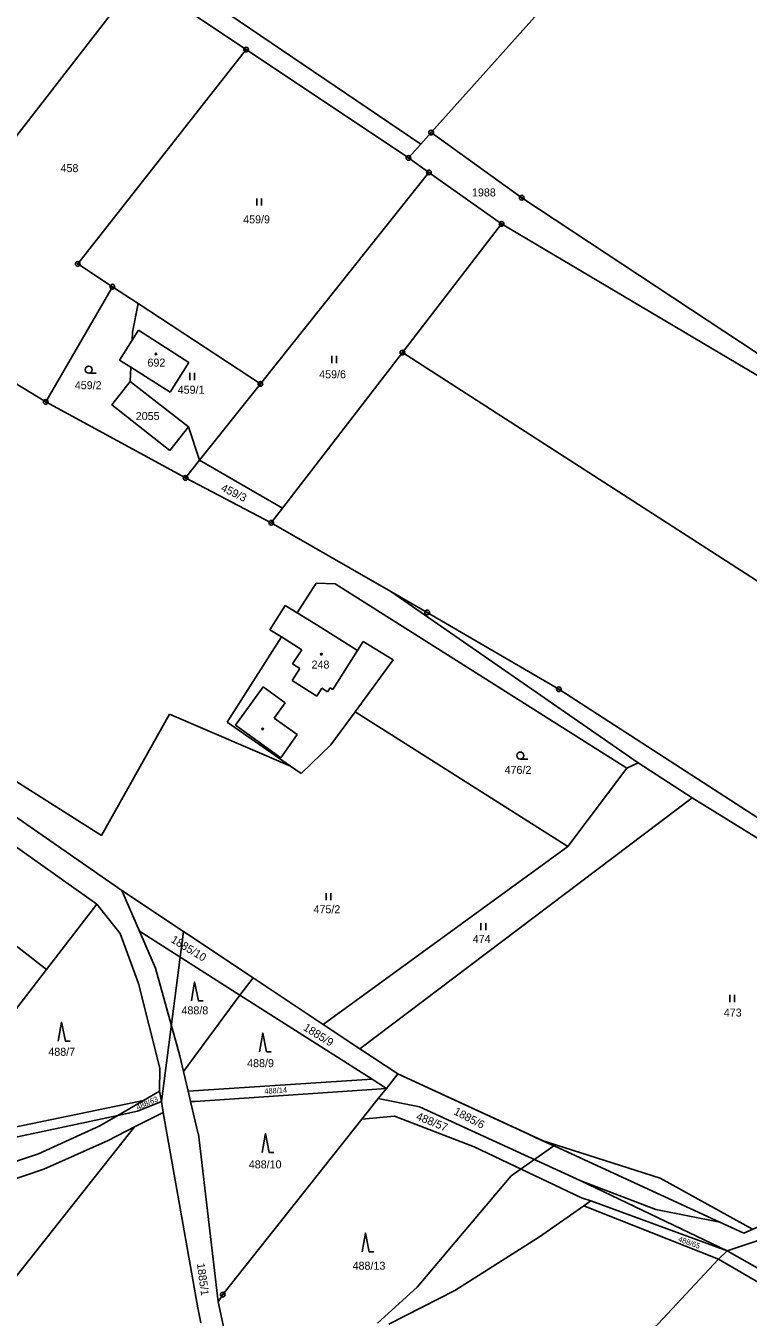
# Model space of a CAD drawing. Extents: x -445050 to -440454, y -1134563 to -1129741.
# Drawn here: x -442735.6 to -442582.2, y -1131669.9 to -1131395.6 of the extents above; entities that cross this region are included whole.
import ezdxf

# ---------------------------------------------------------------- set-up
doc = ezdxf.new("R2010")
doc.units = 0
for name, color, linetype in [('Vrstva 1', 7, 'Continuous'), ('Vrstva 16', 7, 'Continuous'), ('Vrstva 18', 7, 'Continuous'), ('Vrstva 19', 7, 'Continuous'), ('Vrstva 24', 7, 'Continuous'), ('Vrstva 25', 7, 'Continuous'), ('Vrstva 3', 7, 'Continuous'), ('Vrstva 37', 7, 'Continuous'), ('Vrstva 4', 7, 'Continuous'), ('Vrstva 52', 7, 'Continuous')]:
    doc.layers.add(name, color=color, linetype=linetype)

msp = doc.modelspace()

# ---------------------------------------------------------------- linework, layer by layer
at = {"layer": 'Vrstva 1'}
for p, q in [((-442713.03, -1131462.31), (-442712.95, -1131460.66)), ((-442711.72, -1131460.25), (-442700.99, -1131467.07)), ((-442713.31, -1131468.11), (-442713.45, -1131471.14)), ((-442700.99, -1131467.07), (-442705.01, -1131473.39))]:
    msp.add_line(p, q, dxfattribs=at)
for points in [[(-442651.76, -1131420.72), (-442778.95, -1131334.51)], [(-442605.47, -1131368.99), (-442649.54, -1131418.23)], [(-442765.47, -1131454.74), (-442711.64, -1131385.39)], [(-442711.64, -1131385.39), (-442688.85, -1131400.6)], [(-442688.85, -1131400.6), (-442724.6, -1131446.15)], [(-442688.85, -1131400.6), (-442654.36, -1131423.62)], [(-442649.54, -1131418.23), (-442651.76, -1131420.72)], [(-442630.31, -1131432.09), (-442649.54, -1131418.23)], [(-442651.76, -1131420.72), (-442654.36, -1131423.62)], [(-442654.36, -1131423.62), (-442650.02, -1131426.7)], [(-442685.81, -1131471.64), (-442650.02, -1131426.7)], [(-442650.02, -1131426.7), (-442634.59, -1131437.65)], [(-442562.37, -1131476.91), (-442630.31, -1131432.09)], [(-442634.59, -1131437.65), (-442655.64, -1131464.97)], [(-442564.05, -1131479.38), (-442634.59, -1131437.65)], [(-442724.6, -1131446.15), (-442717.25, -1131450.98)], [(-442717.25, -1131450.98), (-442731.4, -1131475.46)], [(-442717.25, -1131450.98), (-442711.81, -1131454.56)], [(-442711.81, -1131454.56), (-442712.95, -1131460.66)], [(-442711.81, -1131454.56), (-442685.81, -1131471.64)], [(-442765.47, -1131454.74), (-442731.4, -1131475.46)], [(-442715.73, -1131466.57), (-442713.03, -1131462.31)], [(-442713.03, -1131462.31), (-442711.72, -1131460.25)], [(-442655.64, -1131464.97), (-442681.13, -1131498.05)], [(-442505.47, -1131561.71), (-442655.64, -1131464.97)], [(-442715.73, -1131466.57), (-442713.31, -1131468.11)], [(-442713.31, -1131468.11), (-442705.01, -1131473.39)], [(-442717.35, -1131476.11), (-442713.45, -1131471.14)], [(-442713.45, -1131471.14), (-442701.08, -1131480.76)], [(-442698.74, -1131487.87), (-442685.81, -1131471.64)], [(-442731.4, -1131475.46), (-442701.71, -1131491.6)], [(-442717.35, -1131476.11), (-442705.03, -1131485.78)], [(-442705.03, -1131485.78), (-442701.08, -1131480.76)], [(-442701.08, -1131480.76), (-442698.74, -1131487.87)], [(-442701.71, -1131491.6), (-442698.74, -1131487.87)], [(-442698.74, -1131487.87), (-442681.13, -1131498.05)], [(-442701.71, -1131491.6), (-442683.5, -1131501.12)], [(-442681.13, -1131498.05), (-442683.5, -1131501.12)], [(-442683.5, -1131501.12), (-442658.12, -1131515.73)], [(-442674, -1131513.97), (-442678.01, -1131520.24)], [(-442669.93, -1131514.08), (-442674, -1131513.97)], [(-442607.99, -1131553.24), (-442669.93, -1131514.08)], [(-442650.39, -1131520.18), (-442658.12, -1131515.73)], [(-442605.54, -1131552.11), (-442658.12, -1131515.73)], [(-442680.56, -1131518.68), (-442683.79, -1131523.85)], [(-442678.01, -1131520.24), (-442680.56, -1131518.68)], [(-442673.59, -1131522.94), (-442678.01, -1131520.24)], [(-442650.39, -1131520.18), (-442622.41, -1131536.5)], [(-442673.59, -1131522.94), (-442665.19, -1131528.29)], [(-442681.32, -1131525.4), (-442692.9, -1131543.48)], [(-442683.79, -1131523.85), (-442681.32, -1131525.4)], [(-442665.19, -1131528.29), (-442663.95, -1131526.35)], [(-442663.95, -1131526.35), (-442657.58, -1131530.23)], [(-442657.58, -1131530.23), (-442665.71, -1131541.3)], [(-442556.5, -1131579.12), (-442622.41, -1131536.5)], [(-442769.33, -1131541.71), (-442715.22, -1131579.29)], [(-442762.98, -1131540.07), (-442719.6, -1131567.6)], [(-442719.6, -1131567.6), (-442705.11, -1131541.83)], [(-442705.11, -1131541.83), (-442679.44, -1131552.84)], [(-442665.71, -1131541.3), (-442670.87, -1131548.32)], [(-442665.71, -1131541.3), (-442620.52, -1131569.9)], [(-442692.9, -1131543.48), (-442679.44, -1131552.84)], [(-442670.87, -1131548.32), (-442677.19, -1131554.4)], [(-442679.44, -1131552.84), (-442677.19, -1131554.4)], [(-442620.52, -1131569.9), (-442607.99, -1131553.24)], [(-442607.99, -1131553.24), (-442605.54, -1131552.11)], [(-442594.09, -1131559.59), (-442605.54, -1131552.11)], [(-442758.42, -1131555.33), (-442720.56, -1131582.16)], [(-442594.09, -1131559.59), (-442664.68, -1131612.89)], [(-442594.09, -1131559.59), (-442506.26, -1131613.79)], [(-442672.47, -1131607.71), (-442620.52, -1131569.9)], [(-442715.22, -1131579.29), (-442687.37, -1131597.8)], [(-442711.5, -1131587.93), (-442715.22, -1131579.29)], [(-442720.56, -1131582.16), (-442731.23, -1131596.02)], [(-442715.62, -1131588.42), (-442720.56, -1131582.16)], [(-442744.14, -1131586.06), (-442731.23, -1131596.02)], [(-442711.69, -1131598.98), (-442715.62, -1131588.42)], [(-442690.15, -1131601.52), (-442711.5, -1131587.93)], [(-442708.13, -1131595.77), (-442711.5, -1131587.93)], [(-442742.62, -1131610.8), (-442731.23, -1131596.02)], [(-442702.94, -1131614.39), (-442708.13, -1131595.77)], [(-442707.18, -1131616.97), (-442711.69, -1131598.98)], [(-442687.37, -1131597.8), (-442690.15, -1131601.52)], [(-442687.37, -1131597.8), (-442672.47, -1131607.71)], [(-442690.15, -1131601.52), (-442702.15, -1131617.73)], [(-442662.1, -1131619.36), (-442690.15, -1131601.52)], [(-442672.47, -1131607.71), (-442664.68, -1131612.89)], [(-442664.68, -1131612.89), (-442656.65, -1131618.23)], [(-442702.15, -1131617.73), (-442702.94, -1131614.39)], [(-442707.25, -1131621.9), (-442707.18, -1131616.97)], [(-442701.16, -1131621.91), (-442702.15, -1131617.73)], [(-442656.65, -1131618.23), (-442659.05, -1131621.3)], [(-442656.65, -1131618.23), (-442588.22, -1131649.72)], [(-442707.25, -1131621.9), (-442710.63, -1131623.87)], [(-442706.86, -1131624.1), (-442707.25, -1131621.9)], [(-442662.1, -1131619.36), (-442701.16, -1131621.91)], [(-442700.64, -1131624.1), (-442701.16, -1131621.91)], [(-442659.05, -1131621.3), (-442699.66, -1131624.1)], [(-442659.05, -1131621.3), (-442662.1, -1131619.36)], [(-442659.05, -1131621.3), (-442660.8, -1131623.46)], [(-442710.63, -1131623.87), (-442744.23, -1131630.81)], [(-442710.63, -1131623.87), (-442716.12, -1131627.06)], [(-442711.91, -1131626.17), (-442706.86, -1131624.1)], [(-442706.45, -1131626.39), (-442706.86, -1131624.1)], [(-442699.03, -1131630.93), (-442700.64, -1131624.1)], [(-442699.66, -1131624.1), (-442700.64, -1131624.1)], [(-442664.24, -1131627.84), (-442660.8, -1131623.46)], [(-442652.04, -1131625.21), (-442660.8, -1131623.46)], [(-442743.17, -1131632.81), (-442716.12, -1131627.06)], [(-442716.12, -1131627.06), (-442719.91, -1131629.27)], [(-442716.12, -1131627.06), (-442711.91, -1131626.17)], [(-442712.53, -1131629.48), (-442706.45, -1131626.39)], [(-442699.12, -1131667.9), (-442706.45, -1131626.39)], [(-442657.35, -1131627.22), (-442664.24, -1131627.84)], [(-442640.38, -1131633.71), (-442657.35, -1131627.22)], [(-442617.77, -1131640.95), (-442652.04, -1131625.21)], [(-442753.33, -1131680.95), (-442712.53, -1131629.48)], [(-442719.91, -1131629.27), (-442732.93, -1131635.18)], [(-442718.17, -1131632.34), (-442712.53, -1131629.48)], [(-442693.82, -1131665.09), (-442664.24, -1131627.84)], [(-442731.84, -1131638.47), (-442718.17, -1131632.34)], [(-442698.99, -1131631.05), (-442699.03, -1131630.93)], [(-442694.81, -1131666.64), (-442698.99, -1131631.05)], [(-442732.93, -1131635.18), (-442761.97, -1131644.83)], [(-442617.58, -1131644.58), (-442640.38, -1131633.71)], [(-442760.3, -1131648.07), (-442731.84, -1131638.47)], [(-442601.79, -1131647.01), (-442617.77, -1131640.95)], [(-442617.77, -1131640.95), (-442586.64, -1131655.78)], [(-442583.14, -1131652.06), (-442560.23, -1131641.95)], [(-442617.09, -1131646.24), (-442626.54, -1131652.86)], [(-442615.59, -1131645.21), (-442617.58, -1131644.58)], [(-442617.09, -1131646.24), (-442615.59, -1131645.21)], [(-442588.49, -1131657.59), (-442617.09, -1131646.24)], [(-442615.59, -1131645.21), (-442586.64, -1131655.78)], [(-442588.22, -1131649.72), (-442601.79, -1131647.01)], [(-442586.64, -1131655.78), (-442559.37, -1131646.74)], [(-442583.14, -1131652.06), (-442588.22, -1131649.72)], [(-442626.54, -1131652.86), (-442644.49, -1131664.21)], [(-442605.32, -1131675.53), (-442588.49, -1131657.59)], [(-442586.64, -1131655.78), (-442588.49, -1131657.59)], [(-442506.53, -1131705.31), (-442588.49, -1131657.59)], [(-442553.17, -1131674.75), (-442586.64, -1131655.78)], [(-442694.81, -1131666.64), (-442693.82, -1131665.09)], [(-442644.49, -1131664.21), (-442658.53, -1131671.42)], [(-442698.48, -1131671.11), (-442699.12, -1131667.9)], [(-442694.81, -1131666.64), (-442691.36, -1131682.4)]]:
    msp.add_lwpolyline(points, dxfattribs=at)
at = {"layer": 'Vrstva 24'}
for centre, radius in [((-442688.85, -1131400.6), 0.5), ((-442688.85, -1131400.6), 0.1), ((-442649.54, -1131418.23), 0.5), ((-442649.54, -1131418.23), 0.1), ((-442654.36, -1131423.62), 0.5), ((-442654.36, -1131423.62), 0.1), ((-442650.02, -1131426.7), 0.5), ((-442650.02, -1131426.7), 0.1), ((-442630.31, -1131432.09), 0.5), ((-442630.31, -1131432.09), 0.1), ((-442634.59, -1131437.65), 0.5), ((-442634.59, -1131437.65), 0.1), ((-442724.6, -1131446.15), 0.5), ((-442724.6, -1131446.15), 0.1), ((-442717.25, -1131450.98), 0.5), ((-442717.25, -1131450.98), 0.1), ((-442655.64, -1131464.97), 0.5), ((-442655.64, -1131464.97), 0.1), ((-442685.81, -1131471.64), 0.5), ((-442685.81, -1131471.64), 0.1), ((-442731.4, -1131475.46), 0.5), ((-442731.4, -1131475.46), 0.1), ((-442701.71, -1131491.6), 0.5), ((-442701.71, -1131491.6), 0.1), ((-442683.5, -1131501.12), 0.5), ((-442683.5, -1131501.12), 0.1), ((-442650.39, -1131520.18), 0.5), ((-442650.39, -1131520.18), 0.1), ((-442622.41, -1131536.5), 0.5), ((-442622.41, -1131536.5), 0.1), ((-442693.82, -1131665.09), 0.5), ((-442693.82, -1131665.09), 0.1)]:
    msp.add_circle(centre, radius, dxfattribs=at)
at = {"layer": 'Vrstva 25'}
for p, q in [((-442686.58, -1131433.71), (-442686.58, -1131432.21)), ((-442685.58, -1131433.71), (-442685.58, -1131432.21)), ((-442670.62, -1131467.2), (-442670.62, -1131465.7)), ((-442669.62, -1131467.2), (-442669.62, -1131465.7)), ((-442722.28, -1131469.35), (-442720.68, -1131469.35)), ((-442700.78, -1131470.81), (-442700.78, -1131469.31)), ((-442699.78, -1131470.81), (-442699.78, -1131469.31)), ((-442630.61, -1131551.34), (-442629.01, -1131551.34)), ((-442671.88, -1131581.33), (-442671.88, -1131579.83)), ((-442670.88, -1131581.33), (-442670.88, -1131579.83)), ((-442638.96, -1131587.69), (-442638.96, -1131586.19)), ((-442637.96, -1131587.69), (-442637.96, -1131586.19)), ((-442586.11, -1131602.95), (-442586.11, -1131601.45)), ((-442585.11, -1131602.95), (-442585.11, -1131601.45))]:
    msp.add_line(p, q, dxfattribs=at)
for points in [[(-442700.48, -1131602.68), (-442699.78, -1131598.68), (-442698.98, -1131602.68), (-442697.98, -1131602.68)], [(-442728.75, -1131611.23), (-442728.05, -1131607.23), (-442727.25, -1131611.23), (-442726.25, -1131611.23)], [(-442686, -1131613.53), (-442685.3, -1131609.53), (-442684.5, -1131613.53), (-442683.5, -1131613.53)], [(-442685.46, -1131634.89), (-442684.76, -1131630.89), (-442683.96, -1131634.89), (-442682.96, -1131634.89)], [(-442664.2, -1131656.02), (-442663.5, -1131652.02), (-442662.7, -1131656.02), (-442661.7, -1131656.02)]]:
    msp.add_lwpolyline(points, dxfattribs=at)
for centre, radius in [((-442707.98, -1131465.27), 0.175), ((-442722.28, -1131468.6), 0.75), ((-442672.86, -1131529.05), 0.175), ((-442685.33, -1131544.95), 0.175), ((-442630.61, -1131550.59), 0.75)]:
    msp.add_circle(centre, radius, dxfattribs=at)
at = {"layer": 'Vrstva 3'}
for points in [[(-442715.73, -1131466.57), (-442713.03, -1131462.31)], [(-442713.03, -1131462.31), (-442711.72, -1131460.25)], [(-442711.72, -1131460.25), (-442700.99, -1131467.07)], [(-442715.73, -1131466.57), (-442713.31, -1131468.11)], [(-442713.31, -1131468.11), (-442705.01, -1131473.39)], [(-442700.99, -1131467.07), (-442705.01, -1131473.39)], [(-442680.56, -1131518.68), (-442683.79, -1131523.85)], [(-442678.01, -1131520.24), (-442680.56, -1131518.68)], [(-442673.59, -1131522.94), (-442678.01, -1131520.24)], [(-442673.59, -1131522.94), (-442665.19, -1131528.29)], [(-442683.79, -1131523.85), (-442681.32, -1131525.4)], [(-442676.99, -1131528.11), (-442681.32, -1131525.4)], [(-442676.99, -1131528.11), (-442678.97, -1131531.13)], [(-442670.46, -1131536.55), (-442665.19, -1131528.29)], [(-442678.97, -1131531.13), (-442677.44, -1131532.11)], [(-442677.44, -1131532.11), (-442679.05, -1131534.64)], [(-442679.05, -1131534.64), (-442673.82, -1131537.97)], [(-442673.82, -1131537.97), (-442672.74, -1131536.26)], [(-442672.74, -1131536.26), (-442671.54, -1131537.03)], [(-442671.54, -1131537.03), (-442671.01, -1131536.2)], [(-442671.01, -1131536.2), (-442670.46, -1131536.55)]]:
    msp.add_lwpolyline(points, dxfattribs=at)
at = {"layer": 'Vrstva 37'}
for centre in [(-442707.98, -1131465.27), (-442672.86, -1131529.05)]:
    msp.add_circle(centre, 0.175, dxfattribs=at)
at = {"layer": 'Vrstva 4'}
for points in [[(-442676.99, -1131528.11), (-442681.32, -1131525.4)], [(-442676.99, -1131528.11), (-442678.97, -1131531.13)], [(-442670.46, -1131536.55), (-442665.19, -1131528.29)], [(-442678.97, -1131531.13), (-442677.44, -1131532.11)], [(-442677.44, -1131532.11), (-442679.05, -1131534.64)], [(-442691.07, -1131544.11), (-442685.21, -1131536.01)], [(-442685.21, -1131536.01), (-442680.55, -1131539.38)], [(-442679.05, -1131534.64), (-442673.82, -1131537.97)], [(-442673.82, -1131537.97), (-442672.74, -1131536.26)], [(-442672.74, -1131536.26), (-442671.54, -1131537.03)], [(-442671.54, -1131537.03), (-442671.01, -1131536.2)], [(-442671.01, -1131536.2), (-442670.46, -1131536.55)], [(-442680.55, -1131539.38), (-442682.89, -1131542.62)], [(-442681.46, -1131551.06), (-442691.07, -1131544.11)], [(-442682.89, -1131542.62), (-442678.03, -1131546.13)], [(-442678.03, -1131546.13), (-442681.46, -1131551.06)]]:
    msp.add_lwpolyline(points, dxfattribs=at)
at = {"layer": 'Vrstva 52'}
for points in [[(-442626.15, -1131632.27), (-442628.86, -1131631.02), (-442656.65, -1131618.23), (-442664.68, -1131612.89), (-442672.47, -1131607.71), (-442687.37, -1131597.8), (-442702.14, -1131587.99), (-442706.86, -1131624.1), (-442706.45, -1131626.39), (-442712.53, -1131629.48), (-442718.17, -1131632.34), (-442731.84, -1131638.47), (-442760.3, -1131648.07)], [(-442626.15, -1131632.27), (-442623.5, -1131633.49), (-442632.52, -1131639.9), (-442652.51, -1131663.49), (-442660.94, -1131671.2)], [(-442581.26, -1131651.23), (-442600.88, -1131640.34), (-442626.15, -1131632.27)]]:
    msp.add_lwpolyline(points, dxfattribs=at)

# ---------------------------------------------------------------- texts
at = {"layer": 'Vrstva 16'}
msp.add_text('1885/1', height=1.7, rotation=277.688, dxfattribs=at).set_placement((-442699.32, -1131658.52))
at = {"layer": 'Vrstva 18'}
for s, p in [('458', (-442728.27, -1131426.64)), ('1988', (-442640.87, -1131431.81)), ('459/9', (-442689.47, -1131437.52)), ('459/2', (-442725.24, -1131472.76)), ('459/6', (-442673.33, -1131470.44)), ('459/1', (-442703.38, -1131473.72)), ('2055', (-442712.29, -1131479.31)), ('476/2', (-442633.94, -1131554.49)), ('475/2', (-442674.53, -1131584.09)), ('474', (-442640.71, -1131590.4)), ('488/8', (-442702.58, -1131605.57)), ('473', (-442587.38, -1131606.04)), ('488/7', (-442730.86, -1131614.37)), ('488/9', (-442688.63, -1131616.78)), ('488/10', (-442688.28, -1131638.29)), ('488/13', (-442666.23, -1131659.82))]:
    msp.add_text(s, height=1.7, dxfattribs=at).set_placement(p)
for s, height, rotation, p in [('459/3', 1.7, 334.2447, (-442694.37, -1131494.28)), ('1885/10', 1.7, 328.5099, (-442704.98, -1131590.13)), ('1885/9', 1.7, 328.095, (-442676.86, -1131608.79)), ('488/14', 1.14, 3.9398, (-442684.93, -1131622.49)), ('488/63', 1.14, 23.7706, (-442711.86, -1131625.9)), ('488/57', 1.7, 337.8024, (-442652.88, -1131627.86)), ('1885/6', 1.7, 332.4366, (-442644.9, -1131626.72)), ('488/65', 1.14, 339.957, (-442597.17, -1131653.75))]:
    msp.add_text(s, height=height, rotation=rotation, dxfattribs=at).set_placement(p)
at = {"layer": 'Vrstva 19'}
for s, p in [('692', (-442709.8, -1131467.96)), ('248', (-442674.95, -1131532.11))]:
    msp.add_text(s, height=1.7, dxfattribs=at).set_placement(p)

doc.saveas('drawing.dxf')
